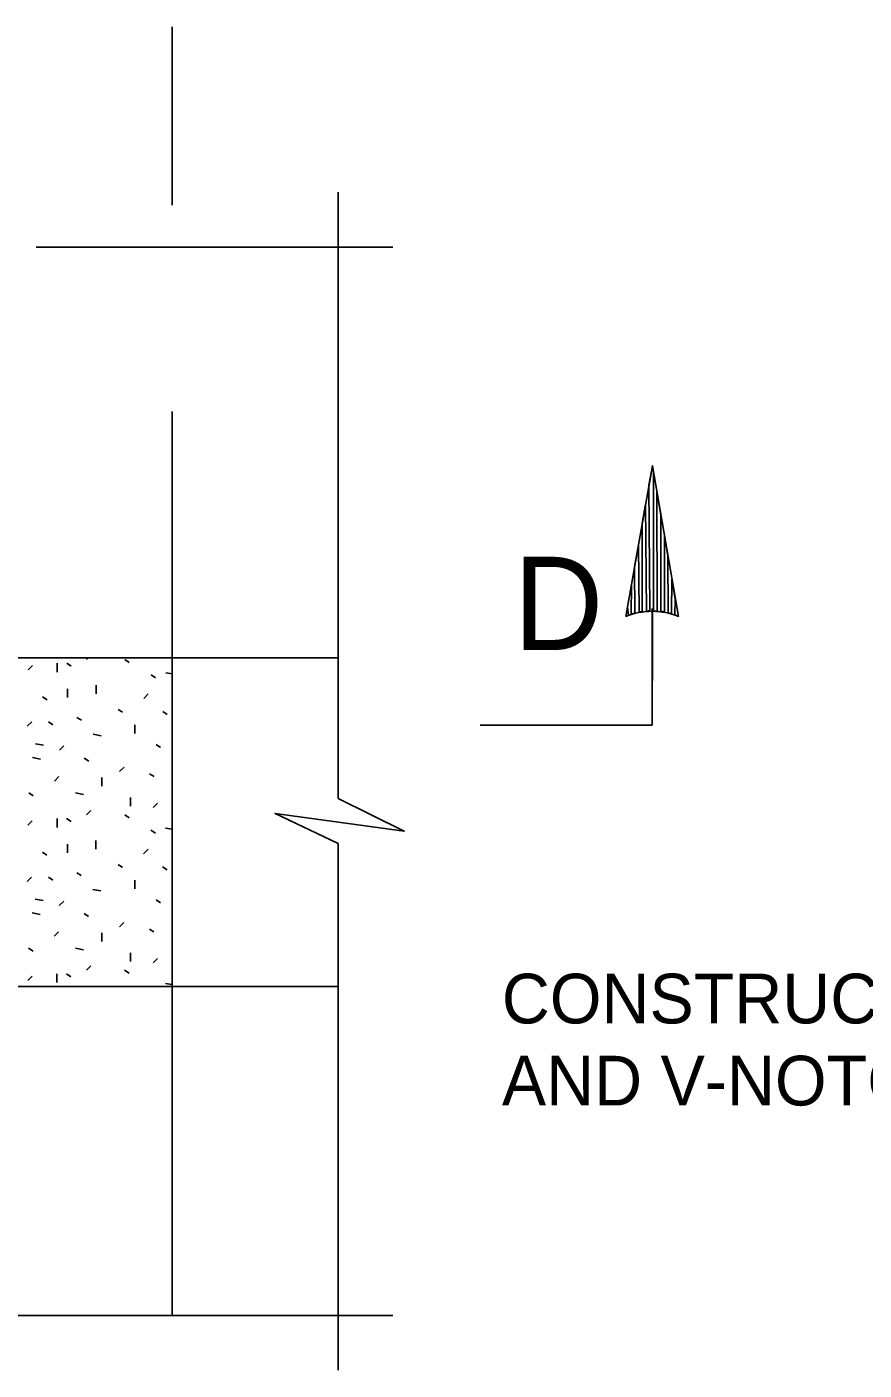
# Model space of a CAD drawing. Extents: x 638167 to 640248, y 296544 to 298920.
# Drawn here: x 639619.3 to 639671.1, y 296860.2 to 296943.3 of the extents above; entities that cross this region are included whole.
import ezdxf

# ---------------------------------------------------------------- set-up
doc = ezdxf.new("R2010")
doc.units = 0
doc.layers.add('1', color=7, linetype='Continuous')

msp = doc.modelspace()

# ---------------------------------------------------------------- linework, layer by layer
at = {"layer": '1'}
for p, q in [((639628.331, 296932.237), (639628.331, 296943.26)), ((639638.601, 296933.038), (639638.601, 296895.551)), ((639619.914, 296929.652), (639641.987, 296929.652)), ((639628.331, 296919.492), (639628.331, 296863.612)), ((639658.02, 296900.094), (639658.02, 296907.304)), ((639658.034, 296907.133), (639658.034, 296902.854)), ((639547.051, 296904.252), (639638.601, 296904.252)), ((639621.223, 296903.378), (639621.223, 296903.92)), ((639622.082, 296903.74), (639621.811, 296903.92)), ((639623.031, 296904.147), (639623.136, 296904.252)), ((639625.669, 296903.966), (639625.398, 296904.146)), ((639619.415, 296903.514), (639619.686, 296903.785)), ((639627.297, 296903.016), (639627.025, 296903.197)), ((639627.93, 296903.333), (639628.331, 296903.26)), ((639621.856, 296901.796), (639621.856, 296902.338)), ((639623.619, 296902.022), (639623.619, 296902.564)), ((639620.59, 296901.66), (639620.319, 296901.841)), ((639626.574, 296901.75), (639626.845, 296902.022)), ((639622.715, 296900.394), (639622.443, 296900.575)), ((639625.263, 296900.892), (639624.991, 296901.072)), ((639628.02, 296900.756), (639627.749, 296900.937)), ((639619.37, 296900.033), (639619.641, 296900.304)), ((639620.952, 296900.123), (639620.68, 296900.304)), ((639626.031, 296899.581), (639626.031, 296900.123)), ((639647.375, 296900.094), (639658.02, 296900.094)), ((639619.867, 296898.948), (639620.364, 296898.857)), ((639623.438, 296899.535), (639623.935, 296899.445)), ((639627.613, 296898.722), (639627.342, 296898.902)), ((639619.686, 296898.089), (639620.183, 296897.998)), ((639621.359, 296898.541), (639621.63, 296898.812)), ((639623.167, 296897.863), (639622.895, 296898.044)), ((639625.082, 296897.23), (639625.353, 296897.501)), ((639621.042, 296896.642), (639621.313, 296896.913)), ((639623.981, 296896.326), (639623.981, 296896.868)), ((639627.207, 296896.913), (639626.935, 296897.094)), ((639619.731, 296895.722), (639619.46, 296895.903)), ((639622.353, 296895.903), (639622.851, 296895.812)), ((639625.76, 296895.089), (639625.76, 296895.631)), ((639623.031, 296894.547), (639623.303, 296894.818)), ((639627.161, 296894.998), (639627.433, 296895.27)), ((639619.407, 296893.913), (639619.678, 296894.184)), ((639621.215, 296893.777), (639621.215, 296894.319)), ((639622.074, 296894.139), (639621.802, 296894.319)), ((639625.669, 296894.366), (639625.398, 296894.546)), ((639627.289, 296893.415), (639627.017, 296893.596)), ((639627.921, 296893.732), (639628.323, 296893.659)), ((639620.582, 296892.059), (639620.31, 296892.24)), ((639621.847, 296892.195), (639621.847, 296892.737)), ((639623.611, 296892.421), (639623.611, 296892.963)), ((639626.565, 296892.149), (639626.837, 296892.421)), ((639638.601, 296892.78), (639638.601, 296860.225)), ((639625.254, 296891.291), (639624.983, 296891.471)), ((639619.361, 296890.432), (639619.633, 296890.703)), ((639620.943, 296890.522), (639620.672, 296890.703)), ((639622.707, 296890.793), (639622.435, 296890.974)), ((639628.012, 296891.155), (639627.74, 296891.336)), ((639623.43, 296889.934), (639623.927, 296889.844)), ((639626.023, 296889.98), (639626.023, 296890.522)), ((639619.859, 296889.347), (639620.356, 296889.256)), ((639621.35, 296888.94), (639621.621, 296889.211)), ((639627.605, 296889.121), (639627.333, 296889.301)), ((639619.678, 296888.488), (639620.175, 296888.397)), ((639623.159, 296888.262), (639622.887, 296888.443)), ((639621.034, 296887.041), (639621.305, 296887.312)), ((639623.972, 296886.725), (639623.972, 296887.267)), ((639625.073, 296887.629), (639625.345, 296887.9)), ((639627.198, 296887.312), (639626.927, 296887.493)), ((639619.723, 296886.121), (639619.451, 296886.302)), ((639622.345, 296886.302), (639622.842, 296886.211)), ((639625.751, 296885.488), (639625.751, 296886.03)), ((639627.153, 296885.397), (639627.424, 296885.669)), ((639623.023, 296884.946), (639623.294, 296885.217)), ((639625.661, 296884.765), (639625.389, 296884.945)), ((639547.051, 296883.932), (639638.601, 296883.932)), ((639619.396, 296884.312), (639619.667, 296884.584)), ((639621.204, 296884.177), (639621.204, 296884.719)), ((639622.063, 296884.538), (639621.791, 296884.719)), ((639627.91, 296884.132), (639628.312, 296884.059)), ((639587.395, 296863.612), (639641.987, 296863.612))]:
    msp.add_line(p, q, dxfattribs=at)
for points in [[(639656.388, 296906.816), (639658.034, 296916.133), (639659.637, 296906.816), (639659.426, 296906.919), (639659.45, 296907.906), (639659.241, 296909.111), (639659.217, 296906.987), (639659.004, 296907.027), (639658.992, 296910.563), (639658.776, 296911.813), (639658.783, 296907.085), (639658.55, 296907.131), (639658.557, 296913.09), (639658.312, 296914.508), (639658.32, 296907.157), (639658.111, 296907.145), (639658.106, 296915.708), (639658.032, 296916.121), (639657.82, 296914.928), (639657.876, 296907.174), (639657.662, 296907.14), (639657.609, 296913.738), (639657.403, 296912.559), (639657.403, 296907.104), (639657.204, 296907.099), (639657.168, 296911.232), (639656.93, 296909.883), (639656.952, 296907.027), (639656.719, 296906.965), (639656.733, 296908.77), (639656.491, 296907.404), (639656.546, 296906.883)], [(639638.601, 296895.551), (639642.684, 296893.552), (639634.692, 296894.639), (639638.601, 296892.78)]]:
    msp.add_lwpolyline(points, dxfattribs=at)
msp.add_arc((639658.014, 296902.818), 4.314, 67.87619, 112.12381, dxfattribs=at)

# ---------------------------------------------------------------- texts
for s, height, p in [('D', 5.765, (639649.433, 296904.742)), ('CONSTRUCTION JOINT', 3.072, (639648.723, 296881.657)), ('AND V-NOTCH', 3.072, (639648.723, 296876.585))]:
    msp.add_text(s, height=height, dxfattribs=at).set_placement(p)

doc.saveas('drawing.dxf')
